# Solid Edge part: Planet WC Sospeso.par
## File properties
Title: Planet
Author: DESYS
Template: Normal.par
Last saved by: s.pallini
Revision: 19
Application: Solid Edge
Tipo di contenuto documento: 0
Precisione: 0,990
Document Number: 8105
Revision: 0
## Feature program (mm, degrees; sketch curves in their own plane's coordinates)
lofted protrusion "unnamed LoftedProtrusion 1"
sketch for "unnamed Protrusion 1" plane through (0, 0, 410) normal (0, 0, 1) x-axis (1, 0, 0)
  line (-251.777, -140) -> (-142.8286, -140)
  line (-251.777, 140) -> (-251.777, -140)
  line (-251.777, 140) -> (-142.8286, 140)
  dimension (linear) = 251.777
extrude "unnamed Protrusion 1" add to key point along -normal
sketch for "unnamed Cutout 1" plane through (0, 0, 0) normal (0, -1, 0) x-axis (1, 0, 0)
  line (-251.777, 410) -> (211.175, 360)
extrude "unnamed Cutout 1" cut through
sketch for "ExtrudedCutout_2" plane through (0, 0, 410) normal (0, 0, 1) x-axis (1, 0, 0)
  circle centre (10.3242, 0) radius 175.0475
extrude "ExtrudedCutout_2" cut finite 90 along -normal
lofted cutout "unnamed LoftedCutout 1"
sketch for "unnamed Cutout 2" plane through (0, 0, 0) normal (0, -1, 0) x-axis (1, 0, 0)
extrude "unnamed Cutout 2" cut through
sketch for "ExtrudedCutout_3" plane through (0, 0, 0) normal (0, -1, 0) x-axis (1, 0, 0)
  line (-251.777, 290) -> (-251.777, 180)
  line (-251.777, 290) -> (-197.8938, 290)
  arc centre (-38.4455, 309.6496) radius 160.6546 from (-197.8938, 290) to (-95.4684, 159.4555) ccw
  line (-95.4684, 159.4555) -> (-95.4684, 0)
extrude "ExtrudedCutout_3" cut finite 210 symmetric
sketch for "unnamed Cutout 3" plane through (0, 0, 0) normal (0, 0, 1) x-axis (1, 0, 0)
  line (-95.4684, -105) -> (8.5066, -95.764)
  arc centre (-2.9504, 0) radius 96.4469 from (8.5066, 95.764) to (8.5066, -95.764) cw
  line (-95.4684, 105) -> (8.5066, 95.764)
  line (-95.4684, 105) -> (-95.4684, -105)
extrude "unnamed Cutout 3" cut to key point along +normal
sketch for "ExtrudedProtrusion_2" plane through (0, 0, 190) normal (0, 0, 1) x-axis (1, 0, 0)
  line (-90, -70) -> (60, -70)
  line (60, -70) -> (60, 70)
  line (60, 70) -> (-90, 70)
  line (-90, 70) -> (-90, -70)
  dimension (linear) = 90
  dimension (linear) = 60
extrude "ExtrudedProtrusion_2" add finite 130 along -normal  Treatment1_DraftAngle = 5 deg
fillet "Rotondo_1" radius 40
fillet "Rotondo_2" radius 30
sketch for "unnamed Protrusion 2" plane through (-251.777, 0, 205) normal (-1, 0, 0) x-axis (0, -1, 0)
  circle centre (0, -25) radius 50
extrude "unnamed Protrusion 2" add through along -normal
sketch for "ExtrudedCutout_6" plane through (0, 0, 0) normal (0, -1, 0) x-axis (1, 0, 0)
  line (50, 190) -> (39.3479, 106.2163)
  arc centre (9.5874, 110) radius 30 from (9.5874, 80) to (39.3479, 106.2163) ccw
  line (-43.5709, 80) -> (9.5874, 80)
  arc centre (-43.5709, 110) radius 30 from (-72.9523, 103.9392) to (-43.5709, 80) ccw
  line (-72.9523, 103.9392) -> (-84.6468, 160.6314)
  line (-84.6468, 160.6314) -> (-147.9995, 220.4026)
  line (-147.9995, 220.4026) -> (-125.2315, 220.4026)
  line (-125.2315, 220.4026) -> (-67.5978, 188.5269)
  line (-54.9154, 116.6106) -> (-67.5978, 188.5269)
  arc centre (-47.037, 118) radius 8 from (-54.9154, 116.6106) to (-47.037, 110) ccw
  line (-47.037, 110) -> (-43.079, 110)
  arc centre (-43.079, 115) radius 5 from (-43.079, 110) to (-38.1416, 115.789) ccw
  line (-50, 190) -> (-38.1416, 115.789)
extrude "ExtrudedCutout_6" cut finite 100 symmetric
sketch for "unnamed Cutout 4" plane through (-251.777, 0, 180) normal (-1, 0, 0) x-axis (0, -1, 0)
  circle centre (0, 0) radius 40
extrude "unnamed Cutout 4" cut to key point along -normal
sketch for "unnamed Cutout 5" plane through (-125.2315, 0, 169.4609) normal (-1, 0, 0) x-axis (0, -1, 0)
  arc centre (0, 10.5391) radius 40 from (35.2415, 29.4609) to (-35.2415, 29.4609) cw
  line (-35.2415, 29.4609) -> (35.2415, 29.4609)
extrude "unnamed Cutout 5" cut through along -normal
fillet "Rotondo_3" radius 10
fillet "Rotondo_4" radius 10
fillet "Rotondo_5" radius 30
fillet "Rotondo_6" radius 5
fillet "Rotondo_7" radius 15
fillet "Rotondo_8" radius 40
fillet "Rotondo_9" radius 10
sketch for "Foro_1" plane through (-23.6867, 0.5154, 385.3657) normal (0.107378, 0, 0.994218) x-axis (0, -1, 0)
  hole centre (95.5154, -158.2785) bore radius 10
hole "Foro_1" diameter 20 through
sketch for "unnamed Hole 1" plane through (-23.6867, 0.5154, 385.3657) normal (0.107378, 0, 0.994218) x-axis (0, -1, 0)
  hole centre (-94.4846, -158.2785) bore radius 10
hole "unnamed Hole 1" through
pattern "unnamed Pattern 1" of "Foro_1", "unnamed Hole 1"
sketch for "ExtrudedCutout_11" plane through (-281.006, 0, 264.4663) normal (-1, 0, 0) x-axis (0, -1, 0)
extrude "ExtrudedCutout_11" cut finite 80 along -normal
sketch for "ExtrudedProtrusion_5" plane through (-251.777, 0, 264.4663) normal (-1, 0, 0) x-axis (0, -1, 0)
extrude "ExtrudedProtrusion_5" add finite 70 along -normal
fillet "Rotondo_14" radius 40
fillet "Rotondo_15" radius 20
fillet "Rotondo_16" radius 10
fillet "Rotondo_17" radius 5
fillet "Rotondo_18" radius 8
fillet "Rotondo_19" radius 8
fillet "Rotondo_20" radius 5
fillet "Rotondo_21" radius 8
fillet "Rotondo_22" radius 5
sketch for "Foro_3" plane through (-251.777, 0, 267.7471) normal (-1, 0, 0) x-axis (0, -1, 0)
  hole centre (92.5, 25.1376) bore radius 12.5
hole "Foro_3" finite
sketch for "unnamed Hole 2" plane through (-251.777, 0, 267.7471) normal (-1, 0, 0) x-axis (0, -1, 0)
  hole centre (-92.5, 25.1376) bore radius 12.5
  dimension (linear) = 92.5
hole "unnamed Hole 2" finite
pattern "unnamed Pattern 2" of "Foro_3", "unnamed Hole 2"
fillet "Rotondo_24" radius 20
fillet "Rotondo_25" radius 5
sketch for "unnamed RevolvedCutout 1" plane through (0, 0, 0) normal (0, -1, 0) x-axis (1, 0, 0)
revolve "unnamed RevolvedCutout 1" cut full turn 360 deg
fillet "Rotondo_27" radius 40
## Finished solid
Body 1: solid body, 188 faces, 451 edges, 266 vertices.
  Faces by surface: cylinder 62, blend 53, plane 41, torus 21, sphere 6, spline 5
  Edges by curve: circle 145, line 132, intersection 105, ellipse 55, spline 14
Bounding box of the edges (mm; curved faces can reach further): 479.356 x 435.509 x 367.414, from (-251.777, -217.7574, 41.4478) to (227.5789, 217.7516, 408.8618).
Cylindrical faces by radius (mm): R5 x14, R8 x10, R10 x13, R12.5 x2, R20 x1, R27.5 x1, R30 x8, R40 x9, R50 x1, R96.4469 x1, R160.6546 x1, R175.0475 x1
Toroidal faces (ring radius, tube radius in mm): R-86.5701 r334.7932 x1, R5 r5 x2, R10 r5 x2, R13 r5 x2, R32.5 r5 x1, R45 r5 x1, R48 r8 x2, R60 r20 x2, R86.4469 r10 x3, R148.5627 r71.0441 x2, R166.6567 r40 x1, R180.6546 r20 x2
Spherical faces by radius (mm): R10 x6
Planar faces by outward normal: +x 2, +y 3, +z 3, -x 5, -y 4, -z 8, oblique 16
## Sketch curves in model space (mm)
arc centre (0, 11.044, 386.1694) radius 200 from (0, 50, 190) through (0, 142.1394, 235.1264) to (0, 199.7809, 320)
arc centre (0, -11.044, 386.1694) radius 200 from (0, -199.7809, 320) through (0, -142.1394, 235.1264) to (0, -50, 190)
arc centre (-0.1331, 0, 383.6835) radius 200 from (-189.7233, 0, 320) through (-136.3679, 0, 237.2591) to (-50, 0, 190)
arc centre (0.7573, 0, 414.6668) radius 230 from (210.3717, 0, 320) through (145.5908, 0, 235.996) to (50, 0, 190)
arc centre (20, -20, 190) radius 30 from (20, -50, 190) through (41.8212, -40.5872, 190) to (50, -20, 190)
line (50, -20, 190) -> (50, 20, 190)
arc centre (20, 20, 190) radius 30 from (20, 50, 190) through (41.8212, 40.5872, 190) to (50, 20, 190)
line (20, 50, 190) -> (-45, 50, 190)
arc centre (-45, 45, 190) radius 5 from (-50, 45, 190) through (-48.4312, 48.6369, 190) to (-45, 50, 190)
line (-50, 45, 190) -> (-50, -45, 190)
arc centre (-45, -45, 190) radius 5 from (-50, -45, 190) through (-48.4312, -48.6369, 190) to (-45, -50, 190)
line (-45, -50, 190) -> (20, -50, 190)
circle centre (10.3242, 0, 320) radius 200.0475
arc centre (-86.5701, 0, 236.8988) radius 334.7932 from (200, 0, 410) through (244.451, 0, 186.7839) to (150, 0, 0)
circle centre (0, 0, 410) radius 200
circle centre (0, 0, 0) radius 150
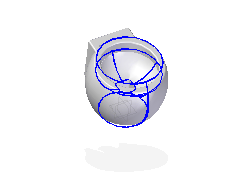
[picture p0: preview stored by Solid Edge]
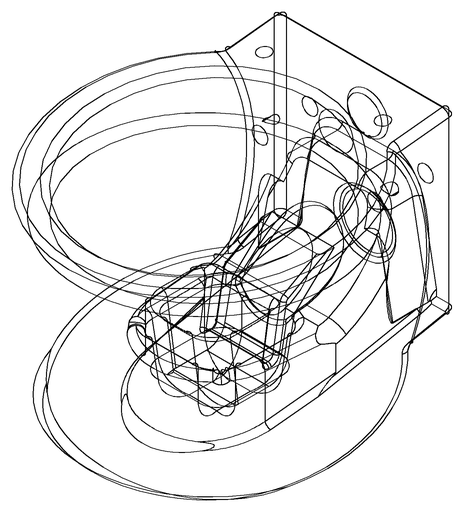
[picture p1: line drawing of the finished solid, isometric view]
